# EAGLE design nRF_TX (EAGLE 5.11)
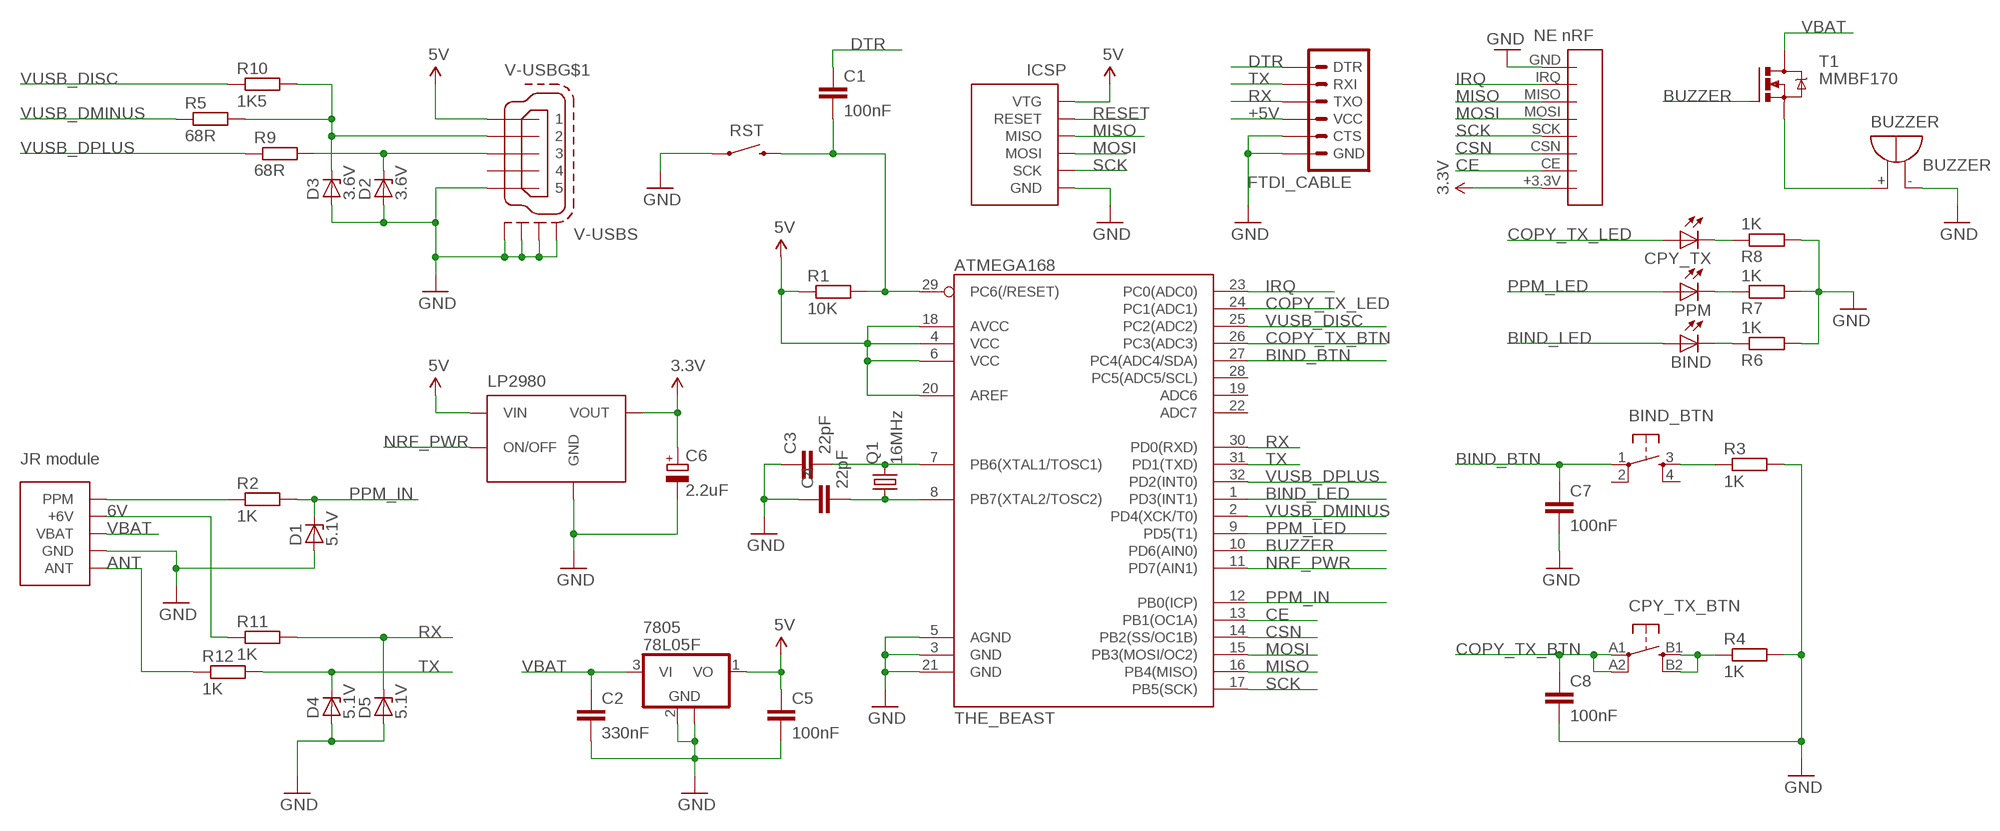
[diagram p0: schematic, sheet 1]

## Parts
7805  78L05F  [SOT89]
BIND  LED3MM  [LED3MM]
BIND_BTN  TACTILE_SWITCH12MM  [TACTILE_SWITCH_12X12]
BUZZER  BUZZER  [BUZZER]
C1  100nF  C-EUC0603  [C0603]
C2  330nF  C-EUC0805  [C0805]
C3  22pF  C-EUC0603  [C0603]
C4  22pF  C-EUC0603  [C0603]
C5  100nF  C-EUC0603  [C0603]
C6  2.2uF  CPOL-EUSMCB  [SMC_B]
C7  100nF  C-EUC0603  [C0603]
C8  100nF  C-EUC0603  [C0603]
CPY_TX  LED3MM  [LED3MM]
CPY_TX_BTN  TACTILE_SWITCH  [TACTILE_SWITCH_TALL_SMD]
D1  5.1V  ZENER-DIODESOD80C  [SOD80C]
D2  3.6V  ZENER-DIODESOD80C  [SOD80C]
D3  3.6V  ZENER-DIODESOD80C  [SOD80C]
D4  5.1V  ZENER-DIODESOD80C  [SOD80C]
D5  5.1V  ZENER-DIODESOD80C  [SOD80C]
FTDI_CABLE  ARDUINO_SERIAL_PROGRAMPTH  [FTDI_CABLE]
ICSP  AVR-ISP-6SMALL_FP  [AVR-ISP-6-SMALL-FP]
JR  JR_MODULE_CONN  [JR_MOODULE_CONN]
LP2980  LP2980  [SOT25]
PPM  LED3MM  [LED3MM]
Q1  16MHz  CRYSTALHC49U70  [HC49U70]
R1  10K  R-EU_R0603  [R0603]
R2  1K  R-EU_R0603  [R0603]
R3  1K  R-EU_R0603  [R0603]
R4  1K  R-EU_R0603  [R0603]
R5  68R  R-EU_R0603  [R0603]
R6  1K  R-EU_R0603  [R0603]
R7  1K  R-EU_R0603  [R0603]
R8  1K  R-EU_R0603  [R0603]
R9  68R  R-EU_R0603  [R0603]
R10  1K5  R-EU_R0603  [R0603]
R11  1K  R-EU_R1206  [R1206]
R12  1K  R-EU_R1206  [R1206]
RST  SWITCH-MOMENTARY-2-SMD-1101NE  [TACTILE-SWITCH-1101NE]
T1  MMBF170  [SOT23]
THE_BEAST  ATMEGA168  [TQFP32-08]
U$2  NRF24L01_MOD_NINE_EAGLES  [NRF24L01_MOD_NINE_EAGLES]
V-USB  MINI-USB-SCHIELD-32005-201  [32005-201]

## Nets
3.3V: C6.+ LP2980.5(VOUT) U$2.+3.3V
6V: JR.+6V R11.1
+5V: 7805.1(VO) C5.1 FTDI_CABLE.4(VCC) ICSP.VCC(VTG) LP2980.1(VIN) R1.1 THE_BEAST.4(VCC) THE_BEAST.6(VCC) THE_BEAST.18(AVCC) THE_BEAST.20(AREF) V-USB.1 ; supply symbol labelled 5V
ANT: JR.ANT R12.1
BIND_BTN: BIND_BTN.1 C7.1 THE_BEAST.27(PC4(ADC4/SDA))
BIND_LED: BIND.A THE_BEAST.1(PD3(INT1))
BUZZER: T1.1(G) THE_BEAST.10(PD6(AIN0))
CE: THE_BEAST.13(PB1(OC1A)) U$2.CE
COPY_TX_BTN: C8.1 CPY_TX_BTN.A1 CPY_TX_BTN.A2 THE_BEAST.26(PC3(ADC3))
COPY_TX_LED: CPY_TX.A THE_BEAST.24(PC1(ADC1))
CSN: THE_BEAST.14(PB2(SS/OC1B)) U$2.CSN
DTR: C1.1 FTDI_CABLE.1(DTR)
GND: 7805.2(GND) 7805.2@1(GND) BUZZER.- C2.2 C3.1 C4.1 C5.2 C6.- C7.2 C8.2 D1.A D2.A D3.A D4.A D5.A FTDI_CABLE.5(CTS) FTDI_CABLE.6(GND) ICSP.GND JR.GND LP2980.2(GND) R3.2 R4.2 R6.2 R7.2 R8.2 RST.P$1 THE_BEAST.3(GND) THE_BEAST.5(AGND) THE_BEAST.21(GND) U$2.GND V-USB.5 V-USB.M1(S:S1) V-USB.M2(S:S2) V-USB.M3(S:S3) V-USB.M4(S:S4)
IRQ: THE_BEAST.23(PC0(ADC0)) U$2.IRQ
MISO: ICSP.MISO THE_BEAST.16(PB4(MISO)) U$2.MISO
MOSI: ICSP.MOSI THE_BEAST.15(PB3(MOSI/OC2)) U$2.MOSI
N$1: C3.2 Q1.2 THE_BEAST.7(PB6(XTAL1/TOSC1))
N$2: C4.2 Q1.1 THE_BEAST.8(PB7(XTAL2/TOSC2))
N$3: JR.PPM R2.1
N$4: BIND_BTN.3 R3.1
N$5: CPY_TX_BTN.B1 CPY_TX_BTN.B2 R4.1
N$6: CPY_TX.K(C) R8.1
N$7: PPM.K(C) R7.1
N$8: BIND.K(C) R6.1
N$10: BUZZER.+ T1.2(S)
N$11: D3.C R5.2 R10.2 V-USB.2
N$12: D2.C R9.2 V-USB.3
NRF_PWR: LP2980.3(ON/OFF) THE_BEAST.11(PD7(AIN1))
PPM_IN: D1.C R2.2 THE_BEAST.12(PB0(ICP))
PPM_LED: PPM.A THE_BEAST.9(PD5(T1))
RESET: C1.2 ICSP.RESET R1.2 RST.P$2 THE_BEAST.29(PC6(/RESET))
RX: D5.C FTDI_CABLE.3(TXO) R11.2 THE_BEAST.30(PD0(RXD))
SCK: ICSP.SCK THE_BEAST.17(PB5(SCK)) U$2.SCK
TX: D4.C FTDI_CABLE.2(RXI) R12.2 THE_BEAST.31(PD1(TXD))
VBAT: 7805.3(VI) C2.1 JR.VBAT T1.3(D)
VUSB_DISC: R10.1 THE_BEAST.25(PC2(ADC2))
VUSB_DMINUS: R5.1 THE_BEAST.2(PD4(XCK/T0))
VUSB_DPLUS: R9.1 THE_BEAST.32(PD2(INT0))
Unconnected: BIND_BTN.2 BIND_BTN.4 THE_BEAST.19(ADC6) THE_BEAST.22(ADC7) THE_BEAST.28(PC5(ADC5/SCL)) V-USB.4

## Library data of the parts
7805 = linear:78L*: POSITOIV-VOLTAGE REGULATORS Output up to 100 mA Source: http://focus.ti.com/lit/ds/symlink/ua78l05.pdf
BIND CPY_TX PPM = KileParts:LED: LED
BIND_BTN CPY_TX_BTN = KileParts:TACTILE_SWITCH: Momentary Switch Button commonly used for reset or general input. Spark Fun Electronics SKU : COM-00097
BUZZER = KileParts:BUZZER
C1-C5 C7 C8 = rcl:C-EU: CAPACITOR, European symbol
C6 = rcl:CPOL-EU: POLARIZED CAPACITOR, European symbol
D1-D5 = diode:ZENER-DIODE: Z-Diode
FTDI_CABLE = KileParts:ARDUINO_SERIAL_PROGRAM
ICSP = KileParts:AVR-ISP-6: AVR ISP-6 Serial Programming Header
JR = KileParts:JR_MODULE_CONN
LP2980 = KileParts:LP2980
Q1 = crystal:CRYSTAL: CRYSTAL; OC_FARNELL: unknown; OC_NEWARK: unknown
R1-R12 = rcl:R-EU_: RESISTOR, European symbol
RST = KileParts:SWITCH-MOMENTARY-2
T1 = KileParts:MMBF170: N-Channel Enhancement Mode Field Effect Transistor
THE_BEAST = KileParts:ATMEGA168
U$2 = KileParts:NRF24L01_MOD_NINE_EAGLES
V-USB = KileParts:MINI-USB-SCHIELD-: MINI USB-B Conector Source: www.cypressindustries.com; OC_FARNELL: unknown; OC_NEWARK: unknown

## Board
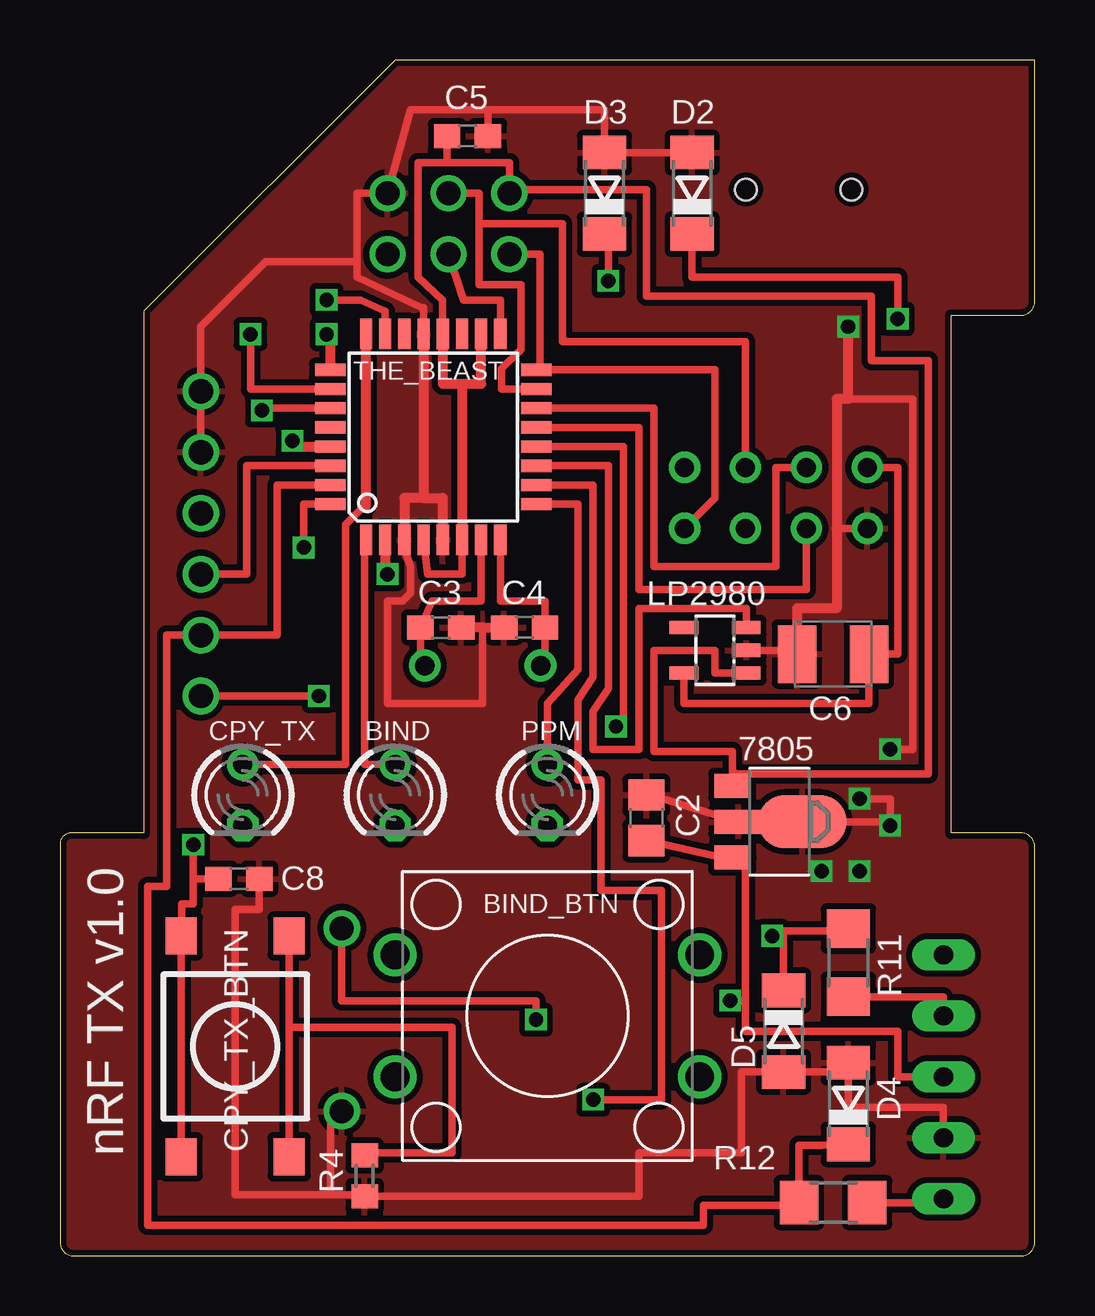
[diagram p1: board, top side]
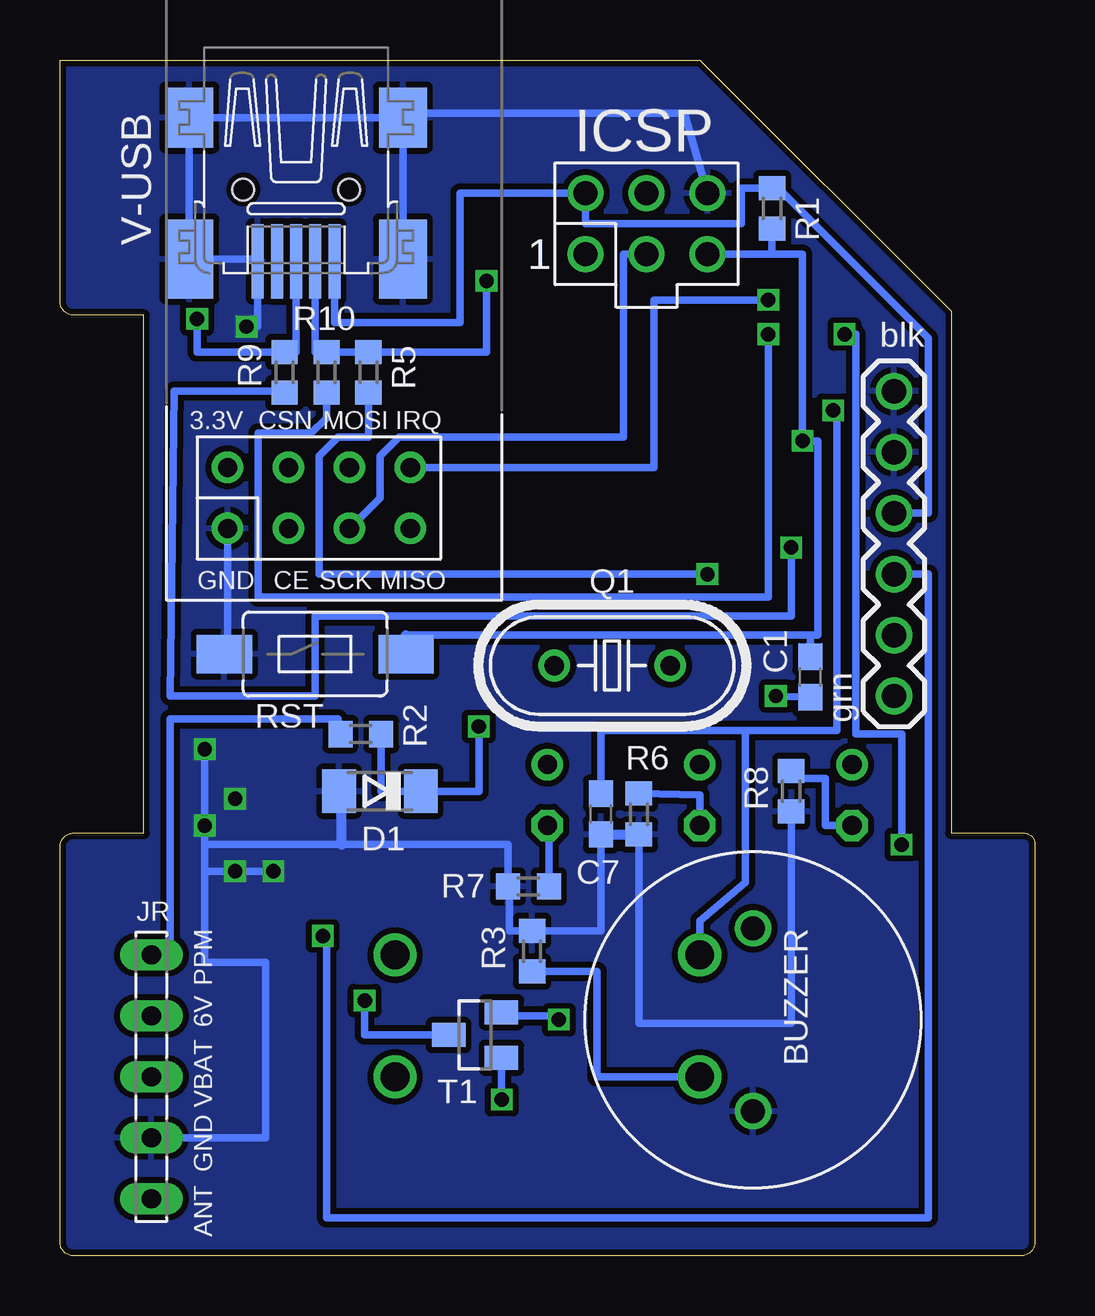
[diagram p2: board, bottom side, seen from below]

Size 40.64 x 49.85 mm. Coordinates in mm from the lower left corner, seen from the top.
Outline: 3.49,39.37 13.97,49.85 40.64,49.84 40.64,39.78 arc-90 40.07,39.21 37.15,39.21 37.15,17.62 40.07,17.62 arc-90 40.64,17.05 40.64,0.57 arc-90 40.07,0 0.57,0 arc-90 0,0.57 0,17.17 arc-90 0.45,17.62 3.49,17.62 3.49,39.36
Copper layers (1*16): Top 0.035mm / dielectric 1.5mm / Bottom 0.035mm
Design rules "Kiles_rule": minimum track width 10mil, minimum drill 12mil, track to track 10mil, track to pad 10mil, pad to pad 10mil, via to via 10mil, smd to smd 0mil, copper to edge 10mil, drill to drill 10mil, minimum pad ring 10mil, minimum via ring 6mil, stop-mask expansion 2mil, vias tented up to drill 100mil, thermal gap 10mil

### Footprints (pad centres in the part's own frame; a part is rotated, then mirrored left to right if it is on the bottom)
SOT89 = smd 1 x 1.5: 1 -1.499,-1.981; 3 1.499,-1.981 | smd 1 x 2: 2 0,-1.727 | smd 2.2 x 3.7: 2@1 0,0.94
LED3MM = drill 0.8 round: A -1.27,0 | drill 0.8 octagon: K 1.27,0
TACTILE_SWITCH_12X12 = drill 1.2 round: 1 -6.35,2.54; 2 6.35,2.54; 3 -6.35,-2.54; 4 6.35,-2.54
BUZZER = drill 1 round: + -3.81,0; - 3.81,0
C0603 = smd 1.1 x 1: 1 -0.85,0; 2 0.85,0
C0805 = smd 1.3 x 1.5: 1 -0.95,0; 2 0.95,0
SMC_B = smd 1.6 x 2.4: + -1.5,0; - 1.5,0
TACTILE_SWITCH_TALL_SMD = smd 1.55 x 1.3: A1 -4.6,-2.25; A2 4.6,-2.25; B1 -4.6,2.25; B2 4.6,2.25
SOD80C = smd 1.4 x 1.8: A 1.7,0; C -1.7,0
FTDI_CABLE = drill 1.016 round: 1 0,0; 2 2.54,0; 3 5.08,0; 4 7.62,0; 5 10.16,0; 6 12.7,0
AVR-ISP-6-SMALL-FP = drill 1 round: GND 2.54,1.27; MISO -2.54,-1.27; MOSI 0,1.27; RESET 2.54,-1.27; SCK 0,-1.27; VCC -2.54,1.27
JR_MOODULE_CONN = drill 0.8 long: +6V 0,2.54; ANT 0,-5.08; GND 0,-2.54; PPM 0,5.08; VBAT 0,0
SOT25 = smd 0.55 x 1.2: 1 -0.95,-1.3; 2 0,-1.3; 3 0.95,-1.3; 4 0.95,1.3; 5 -0.95,1.3
HC49U70 = drill 0.813 round: 1 -2.413,0; 2 2.413,0
R0603 = smd 1 x 1.1: 1 -0.85,0; 2 0.85,0
R1206 = smd 1.6 x 1.803: 1 -1.422,0; 2 1.422,0
TACTILE-SWITCH-1101NE = smd 2.3 x 1.6: P$1 -3.785,0; P$2 3.785,0
SOT23 = smd 1 x 1.4: 1 -0.95,-1.1; 2 0.95,-1.1; 3 0,1.1
TQFP32-08 = smd 1.27 x 0.508: 1 -4.293,2.8; 2 -4.293,2; 3 -4.293,1.2; 4 -4.293,0.4; 5 -4.293,-0.4; 6 -4.293,-1.2; 7 -4.293,-2; 8 -4.293,-2.8; 17 4.293,-2.8; 18 4.293,-2; 19 4.293,-1.2; 20 4.293,-0.4; 21 4.293,0.4; 22 4.293,1.2; 23 4.293,2; 24 4.293,2.8 | smd 0.508 x 1.27: 9 -2.8,-4.293; 10 -2,-4.293; 11 -1.2,-4.293; 12 -0.4,-4.293; 13 0.4,-4.293; 14 1.2,-4.293; 15 2,-4.293; 16 2.8,-4.293; 25 2.8,4.293; 26 2,4.293; 27 1.2,4.293; 28 0.4,4.293; 29 -0.4,4.293; 30 -1.2,4.293; 31 -2,4.293; 32 -2.8,4.293
NRF24L01_MOD_NINE_EAGLES = drill 0.8 round: +3.3V 1.27,3.81; CE -1.27,1.27; CSN 1.27,1.27; GND -1.27,3.81; IRQ 1.27,-3.81; MISO -1.27,-3.81; MOSI 1.27,-1.27; SCK -1.27,-1.27
32005-201 = smd 3.1 x 0.5: 1 3,1.6; 2 3,0.8; 3 3,0; 4 3,-0.8; 5 3,-1.6 | smd 2.5 x 2: M1 -3,-4.45; M2 -3,4.45 | smd 3.3 x 2: M3 2.9,4.45; M4 2.9,-4.45 | hole 0.9: 0,2.2; 0,-2.2

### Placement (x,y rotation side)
7805  30,18.1 270 top
BIND  13.97,19.21 270 top
BIND_BTN  20.32,10 0 top
BUZZER  11.75,9.84 270 bottom
C1  9.37,24.13 90 bottom
C2  24.45,18.26 90 top
C3  15.87,26.19 180 top
C4  19.37,26.19 0 top
C5  16.99,46.67 0 top
C6  32.23,25.08 180 top
C7  18.1,18.41 270 bottom
C8  7.46,15.72 0 top
CPY_TX  7.62,19.21 270 top
CPY_TX_BTN  7.3,8.73 270 top
D1  27.3,19.37 180 bottom
D2  26.35,44.29 90 top
D3  22.7,44.29 90 top
D4  32.86,6.35 90 top
D5  30.16,9.37 270 top
FTDI_CABLE  5.87,23.34 90 bottom
ICSP  16.19,43.02 0 bottom
JR  36.83,7.46 0 bottom
LP2980  27.3,25.24 90 top
PPM  20.32,19.21 270 top
Q1  17.62,24.61 0 bottom
R1  10.95,43.66 270 bottom
R2  28.1,21.75 0 bottom
R3  20.95,12.7 90 bottom
R4  12.7,3.33 270 top
R5  27.78,36.83 90 bottom
R6  16.51,18.42 270 bottom
R7  21.11,15.4 180 bottom
R8  10.16,19.37 270 bottom
R9  31.27,36.83 90 bottom
R10  29.53,36.83 90 bottom
R11  32.86,12.22 90 top
R12  32.23,2.22 180 top
RST  30,25.08 0 bottom
T1  23.34,9.21 90 bottom
THE_BEAST  15.56,34.13 90 top
U$2  29.84,31.59 90 bottom
V-USB  30.8,44.45 270 bottom

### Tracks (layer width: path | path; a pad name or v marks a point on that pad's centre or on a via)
3.3V
  Top 0.305: LP2980.5 26,23.02 33.73,23.02 C6.+ 34.92,25.08 34.92,32.86 U$2.+3.3V
6V
  Top 0.305: R11.1 36.83,10.8 JR.+6V
+5V
  Top 0.305: THE_BEAST.6 16.76,28.42 15.32,28.42 THE_BEAST.4 | 16.14,45.56 14.92,45.56 14.92,40.8 15.96,39.85 THE_BEAST.20 | 27.3,24.29 27.3,25.24 24.77,25.24 24.77,21.03 28.02,21.03 28.02,20.09 28.1,20.09 36.2,20.09 36.2,37.31 33.81,37.31 33.81,40.01 24.45,40.01 24.45,44.45 18.73,44.45 ICSP.VCC 18.73,45.56 16.14,45.56 | 27.3,24.29 | 27.3,24.29 LP2980.1 | 16.14,45.56 C5.1
  Top 0.406: 16.76,36.35 THE_BEAST.6 | 16.76,36.35 15.96,36.35 THE_BEAST.20 | THE_BEAST.18 17.56,36.35 16.76,36.35 | 7805.1 28.1,19.6 28.1,20.09
  Bottom 0.305: FTDI_CABLE.4 4.45,30.96 4.45,38.26 10.64,44.45 | 10.95,44.45 R1.1 12.22,44.51 12.22,43.02 18.73,43.02 ICSP.VCC 23.97,44.29 23.97,38.89 29.2,38.89 V-USB.1
  Bottom 0.406: 10.64,44.45 10.95,44.45
ANT
  Top 0.305: R12.1 36.83,2.22
  Top 0.406: 36.83,2.22 JR.ANT
BIND_BTN  (via drill 0.6)
  Top 0.305: THE_BEAST.27 8.41,35.33 v8.41,35.24
  Bottom 0.305: v8.41,35.24 8.26,35.24 8.26,21.91 12.06,21.91 | 12.06,21.91 12.06,19.21 12.06,15.56 13.97,13.97 BIND_BTN.1 | C7.1 18.1,21.91 12.06,21.91
BIND_LED
  Top 0.305: THE_BEAST.1 12.7,29.84 12.7,20.48 BIND.A
BUZZER  (via drill 0.6)
  Top 0.305: THE_BEAST.10 22.23,32.13 22.23,24.13 21.59,23.18 21.59,19.84 22.54,19.84 22.54,15.24 25.08,15.24 25.08,8.89 25.08,6.51 v22.23,6.51
  Bottom 0.305: v22.24,6.51 T1.1
  Bottom 0.406: v22.23,6.51 v22.24,6.51
CE
  Top 0.305: U$2.CE 31.11,27.78 24.13,27.78 24.13,34.53 THE_BEAST.13
COPY_TX_BTN  (via drill 0.6)
  Top 0.305: 5.05,4.29 CPY_TX_BTN.A2 CPY_TX_BTN.A1 5.08,13.49 5.08,14.29 5.08,14.66 5.56,14.66 5.56,15.72 | v7.94,38.42 7.94,36.13 THE_BEAST.26 | 5.56,15.72 C8.1 | 5.56,15.72 v5.56,17.15
  Top 0.406: v5.56,17.15
  Bottom 0.305: v7.94,38.42 7.46,38.42 7.46,21.75 5.56,21.75 v5.56,17.15
COPY_TX_LED
  Top 0.305: CPY_TX.A 11.91,20.48 11.91,30.48 12.7,31.27 12.76,31.27 | THE_BEAST.24 12.86,38.42
  Top 0.406: 12.76,31.27 THE_BEAST.24
CSN
  Top 0.305: U$2.CSN 29.84,32.86 29.84,28.73 24.77,28.73 24.77,35.33 THE_BEAST.14
DTR  (via drill 0.6)
  Top 0.305: FTDI_CABLE.1 v10.79,23.34
  Bottom 0.305: v10.79,23.34 10.85,23.34 C1.1
GND  (via drill 0.6)
  Top 0.305: 12.38,41.43 12.38,44.29 ICSP.GND 14.61,47.78 17.84,47.78 | 11.27,2.54 11.27,6.03 BUZZER.- | 11.27,2.54 7.3,2.54 7.3,4.13 7.3,14.45 8.31,14.45 C8.2 | 32.38,30.32 U$2.GND | LP2980.2 30.73,25.24 C6.- | D3.A 23.18,45.99 D2.A | D3.A | D3.A 22.7,47.78 17.84,47.78 | 17.84,47.78 C5.2 | 14.45,29.84 THE_BEAST.3 14.45,29.21 14.61,28.73 14.61,27.62 14.29,27.31 13.65,27.31 13.65,23.02 17.62,23.02 17.62,26.19 | FTDI_CABLE.6 FTDI_CABLE.5 5.87,38.74 8.57,41.43 12.38,41.43 | 32.86,35.72 35.56,35.72 35.56,21.11 v34.61,21.11 | C2.2 24.61,19.21 7805.2 | 34.61,18.1 7805.2@1 | v33.34,19.05 34.61,19.05 34.61,18.1 | 34.61,18.1 34.61,17.78 | THE_BEAST.21 15.16,39.53 15.08,39.53 12.38,40.8 12.38,41.43 | JR.GND 36.83,6.19 32.86,6.19 D4.A | 32.86,7.67 D5.A 28.42,7.67 28.42,4.29 24.13,4.29 24.13,2.86 24.13,2.48 R4.2 | 11.27,2.54 12.7,2.54
  Top 0.406: C3.1 17.62,26.19 C4.1 | THE_BEAST.21 15.16,31.59 | 15.16,31.59 15.96,31.59 THE_BEAST.5 | THE_BEAST.3 14.36,31.59 15.16,31.59 | C6.- 30.73,26.99 32.38,26.99 32.38,30.32 32.38,35.72 32.86,35.72 v32.86,38.74 | v34.61,17.94 34.61,18.1 | 7805.2@1 7805.2 | 32.86,7.67 D4.A | 12.7,2.54 R4.2
  Bottom 0.305: U$2.GND 33.66,25.08 RST.P$1 | 28.89,19.21 D1.A | 34.61,16.03 34.61,12.22 32.07,12.22 32.07,4.92 JR.GND | v34.61,21.11 v34.61,17.94 34.61,17.15 | ICSP.GND 14.61,47.63 26.35,47.63 | 34.61,17.15 28.89,17.15 21.96,17.15 R7.2 21.91,15.4 21.91,13.55 R3.2 18.1,13.55 C7.2 | V-USB.5 32.4,38.74 v32.86,38.74 | 32.4,41.55 V-USB.M4 V-USB.M1 V-USB.M2 V-USB.M3 | R8.2 10.16,16.93 10.16,9.68 16.51,9.68 R6.2 | 34.61,16.03 v33.34,16.03 v31.75,16.03 | 34.61,16.03 34.61,17.15
  Bottom 0.406: 28.89,17.15 28.89,19.21 | V-USB.5 32.4,41.55 | V-USB.M2 26.35,47.63 | R6.2 16.67,17.57 C7.2
  pour Bottom: 30.32,21.43 35.24,21.43 35.24,15.08 30.32,15.08
  pour Top: 30.32,19.37 35.24,19.37 35.24,15.08 30.32,15.08
  pour Top (isolate 0.254): 3.49,17.62 3.49,39.37 13.97,49.85 40.64,49.85 40.64,39.78 arc-90 40.07,39.21 37.15,39.21 37.15,17.62 40.07,17.62 arc-90 40.64,17.05 40.64,0.57 arc-90 40.07,0 0.57,0 arc-90 0,0.57 0,17.17 arc-90 0.45,17.62
  pour Bottom (isolate 0.254): 37.15,17.62 37.15,39.21 40.07,39.21 arc90 40.64,39.78 40.64,49.85 13.97,49.85 3.49,39.37 3.49,17.62 0.45,17.62 arc90 0,17.17 0,0.57 arc90 0.57,0 40.07,0 arc90 40.64,0.57 40.64,17.05 arc90 40.07,17.62
IRQ  (via drill 0.6)
  Top 0.305: THE_BEAST.23 13.56,39.37 12.54,39.85 v11.11,39.85
  Bottom 0.305: U$2.IRQ 15.88,32.86 15.88,39.85 v11.11,39.85
MISO
  Top 0.305: ICSP.MISO 20.01,41.75 20,37.94 20,36.93 27.3,36.93 27.3,31.59 U$2.MISO
  Top 0.406: THE_BEAST.16 20,36.93
MOSI
  Top 0.305: ICSP.MOSI 17.46,44.29 17.46,43.02 | 17.46,43.02 17.46,40.48 19.21,40.48 19.21,37.78 18.41,36.99 18.41,36.13 THE_BEAST.15 | 28.57,35.08 U$2.MOSI | 28.57,35.08 28.57,38.1 20.95,38.1 20.95,43.02 17.46,43.02 | 28.57,35.08
N$1
  Top 0.305: THE_BEAST.7 17.56,27.31 15.5,27.31 C3.2 15.03,24.61 Q1.2
N$2
  Top 0.305: THE_BEAST.8 18.36,27.31 20.22,27.31 C4.2 | C4.2 20.03,26.19 | Q1.1 20.22,24.61 C4.2
N$3
  Bottom 0.305: R2.1 29.05,22.38 36.04,22.38 36.04,13.18 36.04,12.54 JR.PPM
N$4
  Bottom 0.305: BIND_BTN.3 18.26,7.46 18.26,11.85 R3.1
N$5
  Top 0.305: CPY_TX_BTN.B2 9.55,9.53 | 9.55,9.53 CPY_TX_BTN.B1 | 9.55,9.53 16.35,9.53 16.35,4.29 12.7,4.29 R4.1
N$6
  Bottom 0.305: CPY_TX.K 8.73,17.94 8.73,19.9 10.16,19.9
  Bottom 0.406: 10.16,19.9 R8.1
N$7
  Bottom 0.305: PPM.K 20.26,17.94 R7.1
N$8
  Bottom 0.305: BIND.K 13.97,19.21 R6.1
N$10  (via drill 0.6)
  Top 0.305: BUZZER.+ 11.75,10.64 19.84,10.64 v19.84,9.84
  Bottom 0.305: v19.84,9.84 19.84,10 22.24,10
  Bottom 0.406: 22.24,10 T1.2
N$11  (via drill 0.6)
  Top 0.305: v22.86,40.64 22.86,42.59 D3.C
  Bottom 0.305: R5.2 22.86,37.68 v22.86,40.64 | R5.2 R10.2 30,37.68 V-USB.2 | R5.2
N$12  (via drill 0.6)
  Top 0.305: D2.C 26.35,40.8 34.92,40.8 v34.92,39.05
  Bottom 0.305: v34.92,39.05 34.92,37.68 R9.2 30.8,37.68 V-USB.3
NRF_PWR
  Top 0.305: THE_BEAST.11 22.86,32.93 22.86,23.65 22.23,22.7 22.23,21.11 | 22.23,21.11 | LP2980.3 28.61,26.99 24.13,26.99 24.13,21.11 22.23,21.11
PPM_IN  (via drill 0.6)
  Top 0.305: THE_BEAST.12 23.5,33.73 23.5,22.07 v23.18,22.07
  Bottom 0.305: R2.2 27.25,19.37 D1.C 23.18,19.37 v23.18,22.07
PPM_LED
  Top 0.305: THE_BEAST.9 21.59,31.33 21.59,24.45 20.32,23.02 PPM.A
RESET  (via drill 0.6)
  Top 0.406: THE_BEAST.29 9.68,33.73 v9.68,33.97
  Bottom 0.305: 10.95,41.75 9.68,41.75 9.68,34.13 v9.68,33.97 9.05,33.97 9.05,25.88 9.37,25.88 | 10.95,41.75 ICSP.RESET | R1.2 | 10.95,41.75 R1.2 | C1.2 9.37,25.88 | 9.37,25.88 26.22,25.88
  Bottom 0.406: 26.22,25.88 RST.P$2
RX  (via drill 0.6)
  Top 0.305: 30.16,13.55 D5.C | FTDI_CABLE.3 7.78,28.42 7.78,32.93 THE_BEAST.30 | 30.16,13.55 29.69,13.55 v29.69,13.34 | 30.16,13.55 32.86,13.55
  Top 0.406: 32.86,13.55 R11.2
  Bottom 0.305: v29.69,13.34 29.53,13.34 29.53,1.59 4.45,1.59 4.45,28.42 FTDI_CABLE.3
SCK
  Top 0.305: THE_BEAST.17 18.36,39.85 16.83,39.85 ICSP.SCK
  Bottom 0.305: ICSP.SCK 17.14,41.75 17.14,40.16 17.14,34.13 26.51,34.13 27.3,33.34 27.3,31.59 U$2.SCK
TX
  Top 0.305: THE_BEAST.31 9.05,32.13 9.05,25.88 FTDI_CABLE.2 4.45,25.88 4.45,15.4 3.65,15.4 3.65,1.27 26.83,1.27 26.83,2.11 30.8,2.11 | D4.C 31.75,4.6 30.8,4.6 R12.2
  Top 0.406: D4.C 32.49,4.17 | 30.8,2.11 R12.2
VBAT  (via drill 0.6)  (1 unrouted)
  Top 0.305: v27.94,10.64 28.57,10.64 | 28.57,10.64 28.57,9.37 29.05,9.37 30.8,9.37 32.23,9.37 34.92,9.37 34.92,7.46 JR.VBAT | 28.57,10.64 28.57,16.6 | 28.02,16.51 C2.1
  Top 0.406: 28.57,16.6 7805.3 28.02,16.51
  Bottom 0.305: v27.94,10.64 27.94,9.21 T1.3
  Bottom 0.406: T1.3
VUSB_DISC  (via drill 0.6)
  Top 0.406: v11.11,38.42 11.27,38.42 THE_BEAST.25
  Bottom 0.305: R10.1 29.53,34.93 30.16,34.29 32.38,34.29 32.38,27.46 11.11,27.46 11.11,36.99 v11.11,38.42
VUSB_DMINUS  (via drill 0.6)
  Top 0.305: 13.56,28.42 v13.65,28.42
  Top 0.406: THE_BEAST.2 13.56,28.42
  Bottom 0.305: R5.1 27.78,34.13 29.05,34.13 29.84,33.34 29.84,28.42 14.13,28.42 v13.65,28.42 | v13.65,28.42
VUSB_DPLUS  (via drill 0.6)
  Top 0.305: v10.16,29.53 10.15,31.27 10.15,31.33 THE_BEAST.32
  Bottom 0.305: R9.1 31.11,36.04 35.88,36.04 36.04,23.34 30,23.34 30,26.67 10.16,26.67 v10.16,29.53

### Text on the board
bPlace: blk | grn
tNames: nRF TX v1.0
